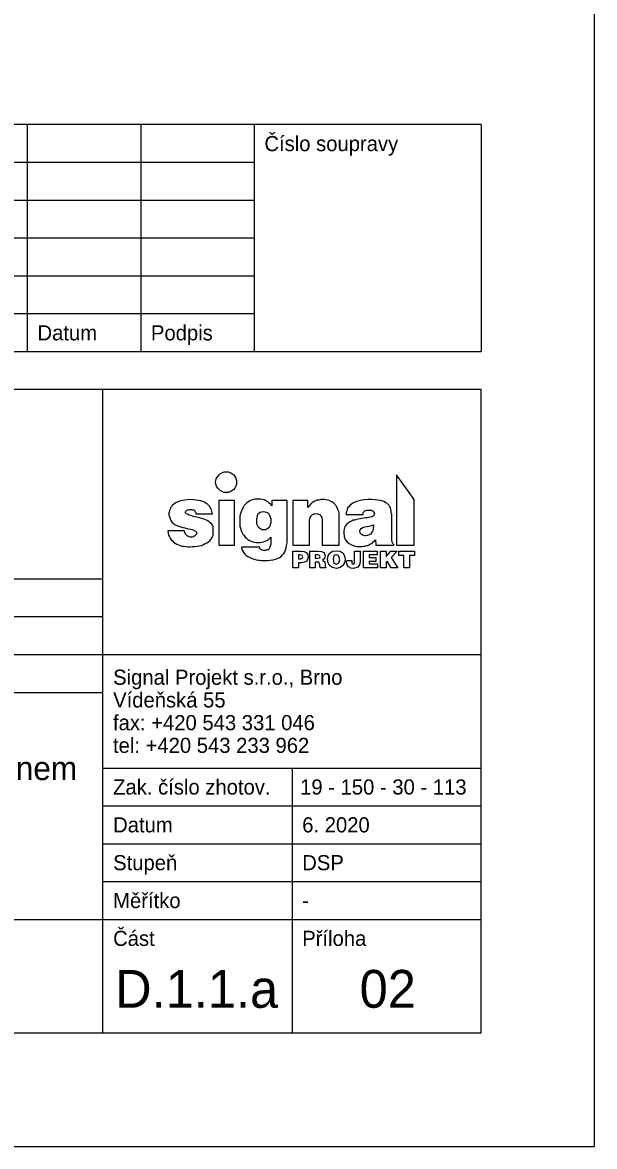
# Model space of a CAD drawing. Extents: x -790051 to -789631, y -987399 to -987102.
# Drawn here: x -789706.2 to -789630.6, y -987398.6 to -987250.1 of the extents above; entities that cross this region are included whole.
import ezdxf

# ---------------------------------------------------------------- set-up
doc = ezdxf.new("R2010")
doc.units = 0
for name, color, linetype in [('Info o rozpiskách', 7, 'Continuous'), ('popis', 7, 'Continuous'), ('Ramečky', 7, 'Continuous'), ('Rámečky-tisk', 7, 'Continuous'), ('Text', 7, 'Continuous'), ('Text barevný', 7, 'Continuous')]:
    doc.layers.add(name, color=color, linetype=linetype)

msp = doc.modelspace()

# ---------------------------------------------------------------- linework, layer by layer
at = {"layer": 'Info o rozpiskách'}
for points in [[(-789679.25, -987309.46), (-789678.98, -987309.47), (-789678.76, -987309.57), (-789678.54, -987309.7), (-789678.29, -987309.87), (-789678.15, -987310.07), (-789678.03, -987310.31), (-789677.94, -987310.58), (-789677.92, -987310.84), (-789677.94, -987311.1), (-789678.03, -987311.38), (-789678.15, -987311.62), (-789678.29, -987311.79), (-789678.54, -987311.99), (-789678.76, -987312.09), (-789678.98, -987312.18), (-789679.25, -987312.2), (-789679.54, -987312.18), (-789679.79, -987312.09), (-789680.05, -987311.99), (-789680.23, -987311.79), (-789680.4, -987311.62), (-789680.57, -987311.38), (-789680.65, -987311.1), (-789680.7, -987310.84), (-789680.65, -987310.58), (-789680.57, -987310.31), (-789680.4, -987310.07), (-789680.23, -987309.87), (-789680.05, -987309.7), (-789679.79, -987309.57), (-789679.54, -987309.47), (-789679.25, -987309.46)], [(-789670.48, -987319.94), (-789669.41, -987319.94), (-789669, -987319.98), (-789668.7, -987320.13), (-789668.52, -987320.37), (-789668.46, -987320.72), (-789668.65, -987321.25), (-789668.95, -987321.42), (-789669.38, -987321.47), (-789669.75, -987321.47), (-789669.75, -987322.16), (-789670.48, -987322.16), (-789670.48, -987319.94)], [(-789668.24, -987319.94), (-789667.16, -987319.94), (-789666.67, -987319.98), (-789666.35, -987320.13), (-789666.19, -987320.58), (-789666.3, -987320.93), (-789666.56, -987321.12), (-789666.24, -987321.34), (-789666.19, -987321.71), (-789666.19, -987321.88), (-789666.17, -987322.05), (-789666.11, -987322.11), (-789666.11, -987322.16), (-789666.86, -987322.16), (-789666.9, -987321.77), (-789667.03, -987321.42), (-789667.18, -987321.4), (-789667.4, -987321.38), (-789667.51, -987321.38), (-789667.51, -987322.16), (-789668.24, -987322.16), (-789668.24, -987319.94)], [(-789664.73, -987319.89), (-789664.23, -987319.96), (-789663.84, -987320.22), (-789663.63, -987320.59), (-789663.56, -987321.02), (-789663.63, -987321.49), (-789663.85, -987321.86), (-789664.23, -987322.12), (-789664.73, -987322.22), (-789665.25, -987322.12), (-789665.65, -987321.84), (-789665.83, -987321.47), (-789665.91, -987321.02), (-789665.83, -987320.58), (-789665.61, -987320.22), (-789665.23, -987319.96), (-789664.73, -987319.89)], [(-789662.33, -987319.94), (-789661.6, -987319.94), (-789661.6, -987321.32), (-789661.67, -987321.75), (-789661.88, -987322.05), (-789662.46, -987322.22), (-789662.83, -987322.18), (-789663.11, -987322.03), (-789663.29, -987321.75), (-789663.37, -987321.36), (-789663.35, -987321.19), (-789662.7, -987321.19), (-789662.66, -987321.56), (-789662.51, -987321.68), (-789662.38, -987321.6), (-789662.33, -987321.42), (-789662.33, -987319.94)], [(-789661.13, -987319.94), (-789659.32, -987319.94), (-789659.32, -987320.44), (-789660.4, -987320.44), (-789660.4, -987320.78), (-789659.49, -987320.78), (-789659.49, -987321.3), (-789660.4, -987321.3), (-789660.4, -987321.64), (-789659.27, -987321.64), (-789659.27, -987322.16), (-789661.13, -987322.16), (-789661.13, -987319.94)], [(-789658.91, -987319.94), (-789658.16, -987319.94), (-789658.16, -987320.65), (-789657.53, -987319.94), (-789656.67, -987319.94), (-789657.49, -987320.78), (-789656.58, -987322.16), (-789657.46, -987322.16), (-789658, -987321.28), (-789658.16, -987321.45), (-789658.16, -987322.16), (-789658.91, -987322.16), (-789658.91, -987319.94)], [(-789656.47, -987319.94), (-789654.41, -987319.94), (-789654.41, -987320.52), (-789655.07, -987320.52), (-789655.07, -987322.16), (-789655.8, -987322.16), (-789655.8, -987320.52), (-789656.47, -987320.52), (-789656.47, -987319.94)], [(-789669.75, -987320.44), (-789669.75, -987320.95), (-789669.43, -987320.95), (-789669.25, -987320.89), (-789669.15, -987320.69), (-789669.23, -987320.52), (-789669.54, -987320.44), (-789669.75, -987320.44)], [(-789667.51, -987320.44), (-789667.51, -987320.89), (-789667.19, -987320.89), (-789666.93, -987320.82), (-789666.88, -987320.69), (-789666.95, -987320.52), (-789667.16, -987320.44), (-789667.51, -987320.44)], [(-789664.73, -987320.43), (-789664.92, -987320.46), (-789665.05, -987320.58), (-789665.16, -987321.04), (-789665.05, -987321.53), (-789664.73, -987321.68), (-789664.38, -987321.49), (-789664.28, -987321.08), (-789664.4, -987320.61), (-789664.53, -987320.46), (-789664.73, -987320.43)]]:
    msp.add_lwpolyline(points, dxfattribs=at)
at = {"layer": 'popis'}
for points in [[(-789656.77, -987309.87), (-789656.77, -987319.14), (-789654.45, -987319.14), (-789654.45, -987313.11), (-789656.77, -987309.87)], [(-789683.29, -987315.02), (-789681.09, -987315.02), (-789681.15, -987314.83), (-789681.19, -987314.66), (-789681.24, -987314.49), (-789681.32, -987314.33), (-789681.41, -987314.18), (-789681.52, -987314.01), (-789681.63, -987313.86), (-789681.8, -987313.69), (-789681.97, -987313.6), (-789682.17, -987313.49), (-789682.4, -987313.39), (-789682.66, -987313.3), (-789682.94, -987313.24), (-789683.26, -987313.19), (-789683.61, -987313.15), (-789684, -987313.13), (-789684.4, -987313.15), (-789684.77, -987313.19), (-789685.09, -987313.26), (-789685.4, -987313.32), (-789685.66, -987313.41), (-789685.89, -987313.52), (-789686.07, -987313.65), (-789686.26, -987313.78), (-789686.43, -987313.93), (-789686.54, -987314.08), (-789686.65, -987314.23), (-789686.71, -987314.4), (-789686.78, -987314.59), (-789686.82, -987314.75), (-789686.86, -987314.89), (-789686.86, -987315.09), (-789686.8, -987315.39), (-789686.71, -987315.69), (-789686.62, -987315.91), (-789686.43, -987316.15), (-789686.26, -987316.28), (-789686.06, -987316.45), (-789685.81, -987316.56), (-789685.55, -987316.64), (-789685.29, -987316.73), (-789685.03, -987316.81), (-789684.77, -987316.88), (-789684.51, -987316.96), (-789684.25, -987316.99), (-789684.02, -987317.03), (-789683.8, -987317.09), (-789683.59, -987317.18), (-789683.39, -987317.25), (-789683.29, -987317.33), (-789683.22, -987317.42), (-789683.2, -987317.52), (-789683.24, -987317.68), (-789683.29, -987317.76), (-789683.33, -987317.85), (-789683.44, -987317.93), (-789683.57, -987318), (-789683.67, -987318.04), (-789683.8, -987318.08), (-789683.93, -987318.08), (-789684.06, -987318.08), (-789684.21, -987318.04), (-789684.38, -987317.98), (-789684.47, -987317.93), (-789684.6, -987317.8), (-789684.69, -987317.68), (-789684.77, -987317.5), (-789684.82, -987317.27), (-789687.01, -987317.27), (-789686.97, -987317.57), (-789686.9, -987317.83), (-789686.8, -987318.06), (-789686.69, -987318.24), (-789686.56, -987318.43), (-789686.41, -987318.6), (-789686.24, -987318.77), (-789686.06, -987318.9), (-789685.83, -987319.01), (-789685.61, -987319.12), (-789685.38, -987319.2), (-789685.14, -987319.27), (-789684.86, -987319.29), (-789684.62, -987319.34), (-789684.38, -987319.36), (-789684.06, -987319.36), (-789683.74, -987319.34), (-789683.43, -987319.34), (-789683.13, -987319.29), (-789682.83, -987319.23), (-789682.55, -987319.18), (-789682.31, -987319.08), (-789682.06, -987318.95), (-789681.86, -987318.86), (-789681.65, -987318.73), (-789681.47, -987318.56), (-789681.34, -987318.41), (-789681.2, -987318.24), (-789681.09, -987318.06), (-789681.02, -987317.83), (-789681, -987317.61), (-789681, -987317.39), (-789681, -987317.33), (-789681, -987317.27), (-789681, -987317.22), (-789681, -987317.16), (-789681, -987317.09), (-789681, -987317.03), (-789681, -987316.99), (-789681, -987316.96), (-789681.02, -987316.71), (-789681.11, -987316.53), (-789681.24, -987316.34), (-789681.39, -987316.21), (-789681.54, -987316.08), (-789681.73, -987315.93), (-789681.9, -987315.84), (-789682.12, -987315.76), (-789682.32, -987315.69), (-789682.55, -987315.61), (-789682.77, -987315.54), (-789682.98, -987315.5), (-789683.22, -987315.44), (-789683.43, -987315.39), (-789683.65, -987315.35), (-789683.84, -987315.3), (-789684.02, -987315.22), (-789684.19, -987315.18), (-789684.32, -987315.11), (-789684.45, -987315.07), (-789684.53, -987315.02), (-789684.64, -987314.94), (-789684.67, -987314.89), (-789684.67, -987314.81), (-789684.67, -987314.74), (-789684.64, -987314.66), (-789684.56, -987314.59), (-789684.49, -987314.55), (-789684.41, -987314.47), (-789684.28, -987314.47), (-789684.13, -987314.44), (-789684, -987314.44), (-789683.85, -987314.44), (-789683.72, -987314.47), (-789683.61, -987314.49), (-789683.5, -987314.55), (-789683.43, -987314.64), (-789683.39, -987314.74), (-789683.31, -987314.85), (-789683.29, -987315.02)], [(-789680.27, -987313.26), (-789680.27, -987319.14), (-789678.18, -987319.14), (-789678.18, -987313.26), (-789680.27, -987313.26)], [(-789673.24, -987313.24), (-789673.24, -987313.97), (-789673.41, -987313.77), (-789673.59, -987313.6), (-789673.8, -987313.43), (-789674.04, -987313.28), (-789674.28, -987313.17), (-789674.51, -987313.11), (-789674.75, -987313.08), (-789675.03, -987313.06), (-789675.29, -987313.08), (-789675.48, -987313.09), (-789675.74, -987313.13), (-789675.93, -987313.23), (-789676.15, -987313.28), (-789676.35, -987313.43), (-789676.58, -987313.54), (-789676.76, -987313.73), (-789676.91, -987313.92), (-789677.06, -987314.16), (-789677.19, -987314.4), (-789677.29, -987314.64), (-789677.4, -987314.96), (-789677.47, -987315.3), (-789677.51, -987315.67), (-789677.51, -987316.06), (-789677.51, -987316.38), (-789677.47, -987316.66), (-789677.4, -987316.92), (-789677.32, -987317.2), (-789677.23, -987317.44), (-789677.1, -987317.68), (-789676.93, -987317.89), (-789676.78, -987318.08), (-789676.62, -987318.24), (-789676.45, -987318.39), (-789676.22, -987318.52), (-789676, -987318.62), (-789675.78, -987318.71), (-789675.53, -987318.77), (-789675.29, -987318.8), (-789675.03, -987318.8), (-789674.81, -987318.8), (-789674.6, -987318.77), (-789674.34, -987318.73), (-789674.12, -987318.64), (-789673.91, -987318.54), (-789673.7, -987318.41), (-789673.56, -987318.28), (-789673.39, -987318.09), (-789673.39, -987318.64), (-789673.39, -987319.03), (-789673.46, -987319.29), (-789673.56, -987319.49), (-789673.63, -987319.64), (-789673.76, -987319.75), (-789673.91, -987319.79), (-789674.08, -987319.85), (-789674.26, -987319.85), (-789674.36, -987319.85), (-789674.49, -987319.83), (-789674.6, -987319.79), (-789674.69, -987319.75), (-789674.75, -987319.68), (-789674.84, -987319.61), (-789674.86, -987319.53), (-789674.9, -987319.44), (-789677.27, -987319.44), (-789677.21, -987319.74), (-789677.1, -987319.94), (-789676.97, -987320.17), (-789676.84, -987320.33), (-789676.67, -987320.54), (-789676.45, -987320.65), (-789676.24, -987320.74), (-789676, -987320.89), (-789675.78, -987320.97), (-789675.53, -987321.02), (-789675.31, -987321.08), (-789675.05, -987321.14), (-789674.84, -987321.15), (-789674.66, -987321.17), (-789674.43, -987321.19), (-789674.26, -987321.19), (-789673.85, -987321.17), (-789673.46, -987321.14), (-789673.09, -987321.08), (-789672.79, -987321.01), (-789672.49, -987320.91), (-789672.23, -987320.78), (-789672.03, -987320.63), (-789671.86, -987320.44), (-789671.69, -987320.24), (-789671.56, -987320.02), (-789671.45, -987319.77), (-789671.35, -987319.49), (-789671.32, -987319.2), (-789671.22, -987318.86), (-789671.22, -987318.51), (-789671.22, -987318.09), (-789671.22, -987313.24), (-789673.24, -987313.24)], [(-789670.5, -987313.26), (-789670.5, -987319.14), (-789668.26, -987319.14), (-789668.26, -987316.14), (-789668.26, -987315.82), (-789668.2, -987315.52), (-789668.11, -987315.35), (-789668.03, -987315.2), (-789667.9, -987315.11), (-789667.75, -987315.03), (-789667.57, -987315.02), (-789667.38, -987314.98), (-789667.19, -987315.02), (-789667.06, -987315.05), (-789666.9, -987315.11), (-789666.8, -987315.22), (-789666.73, -987315.35), (-789666.65, -987315.52), (-789666.62, -987315.78), (-789666.62, -987316.04), (-789666.62, -987319.14), (-789664.34, -987319.14), (-789664.34, -987315.59), (-789664.34, -987315.28), (-789664.36, -987314.98), (-789664.41, -987314.7), (-789664.51, -987314.44), (-789664.6, -987314.21), (-789664.71, -987314.01), (-789664.88, -987313.84), (-789664.99, -987313.67), (-789665.14, -987313.54), (-789665.31, -987313.41), (-789665.5, -987313.36), (-789665.68, -987313.26), (-789665.91, -987313.19), (-789666.09, -987313.15), (-789666.28, -987313.11), (-789666.5, -987313.11), (-789666.78, -987313.11), (-789667.06, -987313.19), (-789667.31, -987313.23), (-789667.57, -987313.36), (-789667.81, -987313.49), (-789668.05, -987313.67), (-789668.26, -987313.92), (-789668.5, -987314.18), (-789668.5, -987313.26), (-789670.5, -987313.26)], [(-789663.41, -987315.11), (-789661.19, -987315.11), (-789661.17, -987314.94), (-789661.13, -987314.81), (-789661.06, -987314.72), (-789660.96, -987314.64), (-789660.85, -987314.57), (-789660.7, -987314.53), (-789660.57, -987314.53), (-789660.42, -987314.53), (-789660.25, -987314.53), (-789660.09, -987314.55), (-789659.96, -987314.62), (-789659.88, -987314.66), (-789659.81, -987314.74), (-789659.73, -987314.81), (-789659.73, -987314.9), (-789659.69, -987315), (-789659.73, -987315.09), (-789659.75, -987315.2), (-789659.84, -987315.28), (-789659.94, -987315.35), (-789660.07, -987315.43), (-789660.25, -987315.46), (-789660.46, -987315.5), (-789660.66, -987315.54), (-789660.89, -987315.56), (-789661.13, -987315.59), (-789661.36, -987315.63), (-789661.6, -987315.67), (-789661.84, -987315.73), (-789662.08, -987315.76), (-789662.29, -987315.84), (-789662.51, -987315.87), (-789662.74, -987315.97), (-789662.96, -987316.08), (-789663.15, -987316.23), (-789663.31, -987316.32), (-789663.44, -987316.47), (-789663.54, -987316.62), (-789663.61, -987316.71), (-789663.67, -987316.88), (-789663.7, -987317.03), (-789663.74, -987317.2), (-789663.76, -987317.35), (-789663.76, -987317.52), (-789663.7, -987318), (-789663.56, -987318.39), (-789663.31, -987318.73), (-789663.05, -987318.93), (-789662.74, -987319.12), (-789662.38, -987319.25), (-789662.06, -987319.33), (-789661.73, -987319.34), (-789661.58, -987319.34), (-789661.45, -987319.33), (-789661.3, -987319.33), (-789661.13, -987319.29), (-789661.02, -987319.27), (-789660.85, -987319.25), (-789660.7, -987319.21), (-789660.57, -987319.18), (-789660.44, -987319.1), (-789660.31, -987319.03), (-789660.18, -987318.97), (-789660.03, -987318.88), (-789659.92, -987318.78), (-789659.81, -987318.67), (-789659.66, -987318.56), (-789659.55, -987318.47), (-789659.51, -987319.16), (-789657.12, -987319.16), (-789657.12, -987319.06), (-789657.25, -987318.93), (-789657.31, -987318.84), (-789657.36, -987318.75), (-789657.36, -987318.67), (-789657.4, -987318.56), (-789657.4, -987318.49), (-789657.4, -987318.37), (-789657.4, -987318.23), (-789657.4, -987315.35), (-789657.4, -987315.11), (-789657.46, -987314.87), (-789657.49, -987314.64), (-789657.53, -987314.42), (-789657.59, -987314.23), (-789657.64, -987314.08), (-789657.74, -987313.92), (-789657.9, -987313.75), (-789658.07, -987313.62), (-789658.24, -987313.51), (-789658.46, -987313.39), (-789658.71, -987313.3), (-789658.97, -987313.24), (-789659.3, -987313.21), (-789659.66, -987313.17), (-789660.07, -987313.11), (-789660.53, -987313.13), (-789661.02, -987313.17), (-789661.37, -987313.23), (-789661.73, -987313.28), (-789662.05, -987313.37), (-789662.29, -987313.47), (-789662.53, -987313.6), (-789662.74, -987313.73), (-789662.92, -987313.88), (-789663.05, -987314.03), (-789663.2, -987314.2), (-789663.28, -987314.38), (-789663.31, -987314.53), (-789663.37, -987314.72), (-789663.41, -987314.9), (-789663.41, -987315.11)], [(-789674.39, -987314.7), (-789674.19, -987314.74), (-789673.98, -987314.79), (-789673.8, -987314.89), (-789673.65, -987315.02), (-789673.56, -987315.2), (-789673.48, -987315.41), (-789673.41, -987315.67), (-789673.41, -987315.95), (-789673.41, -987316.19), (-789673.48, -987316.42), (-789673.54, -987316.64), (-789673.63, -987316.81), (-789673.74, -987316.92), (-789673.91, -987317.05), (-789674.08, -987317.11), (-789674.3, -987317.12), (-789674.53, -987317.11), (-789674.71, -987317.05), (-789674.9, -987316.92), (-789675.01, -987316.83), (-789675.1, -987316.64), (-789675.2, -987316.47), (-789675.23, -987316.25), (-789675.25, -987316.01), (-789675.23, -987315.74), (-789675.2, -987315.5), (-789675.16, -987315.28), (-789675.09, -987315.07), (-789674.99, -987314.94), (-789674.82, -987314.79), (-789674.64, -987314.74), (-789674.39, -987314.7)], [(-789659.81, -987316.47), (-789659.81, -987316.49), (-789659.81, -987316.55), (-789659.81, -987316.58), (-789659.84, -987316.84), (-789659.86, -987317.11), (-789659.96, -987317.29), (-789660.07, -987317.52), (-789660.22, -987317.68), (-789660.4, -987317.78), (-789660.61, -987317.87), (-789660.81, -987317.93), (-789660.98, -987317.93), (-789661.09, -987317.89), (-789661.21, -987317.83), (-789661.32, -987317.78), (-789661.43, -987317.7), (-789661.52, -987317.61), (-789661.6, -987317.52), (-789661.62, -987317.37), (-789661.58, -987317.12), (-789661.45, -987316.94), (-789661.22, -987316.83), (-789660.98, -987316.75), (-789660.66, -987316.68), (-789660.38, -987316.64), (-789660.09, -987316.55), (-789659.81, -987316.47)]]:
    msp.add_lwpolyline(points, dxfattribs=at)
at = {"layer": 'Ramečky'}
for p, q in [((-789645.59, -987263.6), (-789825.59, -987263.6)), ((-789705.59, -987263.6), (-789705.59, -987293.6)), ((-789690.59, -987263.6), (-789690.59, -987293.6)), ((-789675.59, -987263.6), (-789675.59, -987293.6)), ((-789645.59, -987263.6), (-789645.59, -987293.6)), ((-789675.59, -987268.6), (-789825.59, -987268.6)), ((-789675.59, -987273.6), (-789825.59, -987273.6)), ((-789675.59, -987278.6), (-789825.59, -987278.6)), ((-789675.59, -987283.6), (-789825.59, -987283.6)), ((-789675.59, -987288.6), (-789825.59, -987288.6)), ((-789645.59, -987293.6), (-789825.59, -987293.6)), ((-789645.59, -987298.6), (-789825.59, -987298.6)), ((-789695.59, -987383.6), (-789695.59, -987298.6)), ((-789645.59, -987383.6), (-789645.59, -987298.6)), ((-789825.59, -987323.6), (-789695.59, -987323.6)), ((-789825.59, -987328.6), (-789695.59, -987328.6)), ((-789825.59, -987333.6), (-789695.59, -987333.6)), ((-789825.59, -987338.6), (-789695.59, -987338.6)), ((-789695.59, -987348.6), (-789645.59, -987348.6)), ((-789695.59, -987353.6), (-789645.59, -987353.6)), ((-789695.59, -987358.6), (-789645.59, -987358.6)), ((-789695.59, -987363.6), (-789645.59, -987363.6)), ((-789825.59, -987368.6), (-789645.59, -987368.6)), ((-789825.59, -987383.6), (-789645.59, -987383.6))]:
    msp.add_line(p, q, dxfattribs=at)
for points in [[(-789695.59, -987333.6), (-789645.59, -987333.6)], [(-789670.59, -987348.6), (-789670.59, -987383.6)]]:
    msp.add_lwpolyline(points, dxfattribs=at)
at = {"layer": 'Rámečky-tisk'}
msp.add_lwpolyline([(-790050.59, -987398.6), (-789630.59, -987398.6), (-789630.59, -987101.6)], dxfattribs=at)

# ---------------------------------------------------------------- texts
at = {"layer": 'Text'}
for s, p in [('Číslo soupravy', (-789674.24, -987267.1)), ('Datum', (-789704.24, -987292.1)), ('Podpis', (-789689.24, -987292.1)), ('Signal Projekt s.r.o., Brno', (-789694.24, -987337.6)), ('Vídeňská 55', (-789694.24, -987340.6)), ('fax: +420 543 331 046', (-789694.26, -987343.6)), ('tel: +420 543 233 962', (-789694.26, -987346.6)), ('Zak. číslo zhotov.', (-789694.24, -987352.1)), ('19 - 150 - 30 - 113', (-789669.52, -987352.1)), ('Datum', (-789694.24, -987357.1)), ('6. 2020', (-789669.24, -987357.1)), ('Stupeň', (-789694.24, -987362.1)), ('DSP', (-789669.24, -987362.1)), ('Měřítko', (-789694.24, -987367.1)), ('-', (-789669.24, -987367.1)), ('Část', (-789694.24, -987372.1)), ('Příloha', (-789669.24, -987372.1))]:
    msp.add_text(s, height=2, dxfattribs=at).set_placement(p)
at = {"layer": 'Text barevný'}
for s, height, p in [('Oprava zabezpečovacího zařízení v ŽST Bystřice nad Pernštejnem', 3.1179, (-789823.21, -987350.19)), ('D.1.1.a', 5, (-789693.98, -987380.27)), ('02', 5, (-789661.65, -987380.27))]:
    msp.add_text(s, height=height, dxfattribs=at).set_placement(p)

doc.saveas('drawing.dxf')
